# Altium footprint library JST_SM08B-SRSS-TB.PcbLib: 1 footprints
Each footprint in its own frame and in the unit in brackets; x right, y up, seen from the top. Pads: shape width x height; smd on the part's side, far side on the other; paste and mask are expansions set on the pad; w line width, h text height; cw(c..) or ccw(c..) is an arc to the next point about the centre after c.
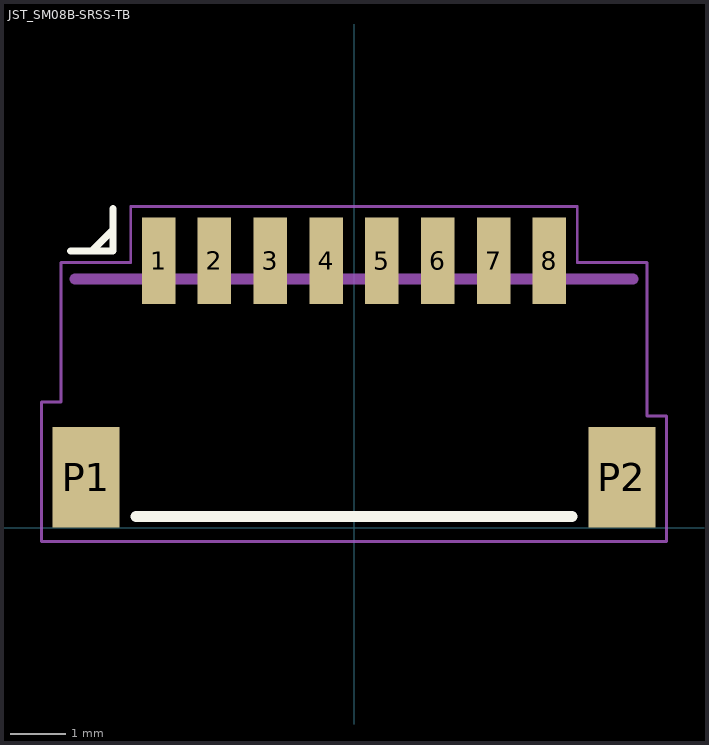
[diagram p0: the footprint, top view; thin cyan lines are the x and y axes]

## JST_SM08B-SRSS-TB [mm]
pads (10):
  rect 0.6x1.55 smd: 1(-3.5,4.775) 2(-2.5,4.775) 3(-1.5,4.775) 4(-0.5,4.775) 5(0.5,4.775) 6(1.5,4.775) 7(2.5,4.775) 8(3.5,4.775)
  rect 1.2x1.8 smd: P1(-4.8,0.9) P2(4.8,0.9)
Top Overlay:
  lines w0.127: -5.08,4.953 -4.318,4.953 -4.318,5.715 ; -4.699,4.953 -4.318,5.334
  lines w0.2: -3.9,0.2 3.9,0.2
Mechanical 13:
  lines w0.2: -5,4.45 5,4.45
Mechanical 15:
  lines w0.05: -5.6,-0.25 5.6,-0.25 5.6,2 5.25,2 5.25,4.75 4,4.75 4,5.75 -4,5.75 -4,4.75 -5.25,4.75 -5.25,2.25 -5.6,2.25 -5.6,-0.25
